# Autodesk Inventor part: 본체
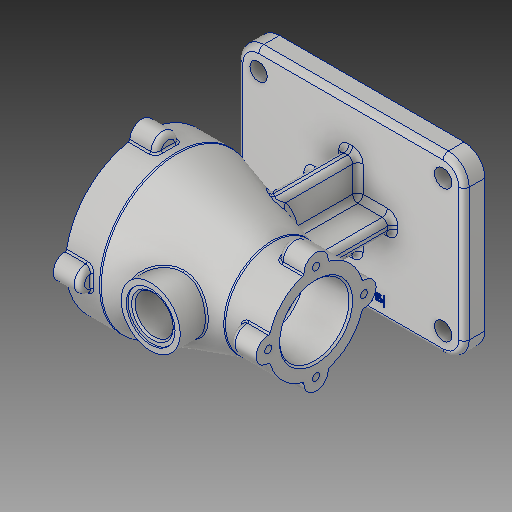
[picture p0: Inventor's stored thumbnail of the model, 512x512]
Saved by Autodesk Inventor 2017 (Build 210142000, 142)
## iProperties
Part Number: 본체
Material: 알루미늄 6061
Document SubType Name: Modeling
Designer: 222
Density: 2.7 g/cm^3
Appearance: 알루미늄 - 평지
Mass: 1030.13 g
Surface Area: 850.653 cm^2
Volume: 381.528 cm^3
Author: 222
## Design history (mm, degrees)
sketch "스케치1"
  geometry: L1 (-50, 0)-(50, 0); L2 (-50, 0)-(-50, 44); L3 (-50, 44)-(-30, 44); L4 (25, 27.5)-(50, 27.5); L5 (50, 27.5)-(50, 0); L6 (-30, 44)-(25, 27.5); 3 further points
  constraints: 12 end point, 2 midpoint, 2 perpendicular, 1 coincident, 1 horizontal, 1 parallel, 1 vertical
  dimensions: "d0" = 100 distance of L1.start L1.end; "d1" = 20 distance of L2.end L3.end; "d2" = 88 diameter of L3 L1; "d3" = 55 diameter of L4 L1; "d90" = 25 distance of L4.start L4.end
revolve "회전1" sketch "스케치1" stored, may be unused: angle "d5" = 90 deg
node "작업 평면1"
sketch "스케치2"
  geometry: L1 (-65, -50)-(65, -50); L2 (65, -50)-(65, 50); L3 (65, 50)-(-65, 50); L4 (-65, 50)-(-65, -50); L5 (-65, -50)-(65, 50); L6 (65, -50)-(-65, 50); 1 further point
  constraints: 12 end point, 2 midpoint, 2 parallel, 1 horizontal, 1 perpendicular
  dimensions: "d7" = 130 distance of L2.end L3.end; "d8" = 100 distance of L1.end L2.end
extrude "돌출1" join sketch "스케치2" distance "d9" = 12; taper "d10" = 0 deg
sketch "스케치3"
  geometry: L1 (-24, -4)-(24, -4); L2 (24, -4)-(24, 4); L3 (24, 4)-(-24, 4); L4 (-24, 4)-(-24, -4); L5 (-24, -4)-(24, 4); L6 (24, -4)-(-24, 4); L7 (4, -25)-(-4, -25); L8 (-4, -25)-(-4, 25); L9 (-4, 25)-(4, 25); L10 (4, 25)-(4, -25); L11 (4, -25)-(-4, 25); L12 (-4, -25)-(4, 25); 1 further point
  constraints: 24 end point, 4 midpoint, 4 parallel, 2 horizontal, 2 perpendicular
  dimensions: "d11" = 8 distance of L1.end L2.end; "d12" = 8 distance of L7.start L7.end; "d13" = 48 distance of L1.start L1.end; "d14" = 50 distance of L9.end L7.start
extrude "돌출2" join sketch "스케치3" stored distance "d15" = 12; taper "d16" = 0 deg
sketch "스케치4"
  geometry: L1 (50, 44)-(50, -44) reference; L2 (50, 0)-(-50, 0); L3 (-50, 27.5)-(-50, -27.5) reference; L4 (50, 0)-(50, 32); L5 (50, 32)-(27, 32); L6 (27, 32)-(27, 26); L7 (27, 26)-(-20, 26); L8 (-20, 26)-(-20, 20); L9 (-20, 20)-(-50, 20); L10 (-50, 0)-(-50, 20); 1 further point
  constraints: 16 end point, 5 perpendicular, 2 midpoint, 2 point on line, 1 horizontal
  dimensions: "d17" = 64 diameter of L5 L2; "d18" = 52 diameter of L7 L2; "d19" = 40 diameter of L9 L2; "d20" = 23 distance of L4.end L5.end; "d21" = 30 distance of L8.end L9.end
revolve "회전2" sketch "스케치4" stored, may be unused: angle "d22" = 90 deg
sketch "스케치5"
  geometry: C1 r 7 at (-27.5, 0); 2 further points
  constraints: 2 horizontal alignment, 1 centre point, 1 other
  dimensions: "d23" = 14 diameter of C1
extrude "돌출3" join sketch "스케치5" distance "d24" = 15; taper "d25" = 0 deg
sketch "스케치6"
  geometry: L1 (109.5, -50)-(97.5, -50) reference; L2 (97.5, -50)-(97.5, 50) reference; L3 (97.5, 50)-(109.5, 50) reference; L4 (109.5, 50)-(109.5, -50) reference; C1 r 20 at (27.5, 0) reference; A1 r 7 centre (27.5, -27.5) between (20.557, -26.609) and (34.443, -26.609) reference; A2 r 27.5 centre (27.5, 0) between (0.891, -6.943) and (20.557, -26.609) reference; A3 r 7 centre (0, 0) between (0.891, 6.943) and (0.891, -6.943) reference; A4 r 27.5 centre (27.5, 0) between (20.557, 26.609) and (0.891, 6.943) reference; A5 r 7 centre (27.5, 27.5) between (34.443, 26.609) and (20.557, 26.609) reference; A6 r 27.5 centre (27.5, 0) between (54.109, 6.943) and (34.443, 26.609) reference; A7 r 7 centre (55, 0) between (54.109, -6.943) and (54.109, 6.943) reference; A8 r 27.5 centre (27.5, 0) between (34.443, -26.609) and (54.109, -6.943) reference; 1 further point
hole "구멍1" sketch "스케치6" at (0, 0) diameter "d29" = 4.134; stored, may be unused: countersink angle "d33" = 90 deg, drill point angle "d35" = 118 deg; dims "d30" = 9, "d31" = 4, "d32" = 2, "d34" = 11
sketch "스케치7"
  geometry: C1 r 7 at (44, 0); 2 further points
  constraints: 2 horizontal alignment, 1 centre point, 1 other
  dimensions: "d39" = 14 diameter of C1
extrude "돌출4" join sketch "스케치7" distance "d40" = 15; taper "d41" = 0 deg
sketch "스케치8"
  geometry: A1 r 7 centre (0, 0) between (-0.557, -6.978) and (-0.557, 6.978) reference; 1 further point
hole "구멍2" sketch "스케치8" at (0, 0) diameter "d42" = 4.134; stored, may be unused: countersink angle "d46" = 90 deg, drill point angle "d48" = 118 deg; dims "d43" = 9, "d44" = 4, "d45" = 2, "d47" = 11
fillet "모깎기1" dims "d52" = 12
sketch "스케치9"
  geometry: L1 (65, 38)-(65, -38) reference; L2 (53, -50)-(-53, -50) reference; L3 (-65, -38)-(-65, 38) reference; L4 (-53, 50)-(53, 50) reference; L5 (24, 4)-(24, -4) reference; L6 (24, -4)-(4, -4) reference; L7 (4, -4)-(4, -25) reference; L8 (4, -25)-(-4, -25) reference; L9 (-4, -25)-(-4, -4) reference; L10 (-4, -4)-(-24, -4) reference; L11 (-24, -4)-(-24, 4) reference; L12 (-24, 4)-(-4, 4) reference; L13 (-4, 4)-(-4, 25) reference; L14 (-4, 25)-(4, 25) reference; L15 (4, 25)-(4, 4) reference; L16 (4, 4)-(24, 4) reference; C1 r 5 at (-53, 38); C2 r 5 at (-53, -38); C3 r 5 at (53, -38); C4 r 5 at (53, 38); A1 r 12 centre (53, 38) between (65, 38) and (53, 50) reference; A2 r 12 centre (53, -38) between (53, -50) and (65, -38) reference; A3 r 12 centre (-53, -38) between (-65, -38) and (-53, -50) reference; A4 r 12 centre (-53, 38) between (-53, 50) and (-65, 38) reference; 1 further point
  constraints: 4 centre point, 4 coincident
  dimensions: "d53" = 10 diameter of C1; "d54" = 10 diameter of C2; "d55" = 10 diameter of C3; "d56" = 10 diameter of C4
extrude "돌출5" cut sketch "스케치9" stored distance "d57" = 15; taper "d58" = 0 deg
node "작업 평면2"
sketch "스케치10"
  geometry: C1 r 17 at (0, 0); 1 further point
  constraints: 1 centre point, 1 coincident
  dimensions: "d60" = 34 diameter of C1
extrude "돌출6" join sketch "스케치10" stored distance "d61" = 15; taper "d62" = 0 deg
sketch "스케치11"
  geometry: 1 further point
hole "구멍3" sketch "스케치11" at (0, 0) diameter "d63" = 22; stored, may be unused: countersink angle "d67" = 90 deg, drill point angle "d69" = 118 deg; dims "d64" = 9, "d65" = 28, "d66" = 1, "d68" = 24.5
node "작업 평면3"
sketch "스케치12"
  geometry: L1 (-53, -50)-(53, -50) reference; 2 further points
  constraints: 1 vertical alignment, 1 other
  dimensions: "d71" = 10 distance from line of L1 point (0, -40)
feature "엠보싱1" sketch "스케치12" dims "d0" = 100, "d1" = 20, "d2" = 88, "d3" = 55, "d72" = 0.5, "d73" = 0, "d90" = 25
fillet "모깎기2" dims "d74" = 3
fillet "모깎기4" dims "d76" = 3
fillet "모깎기5" dims "d77" = 3
fillet "모깎기6" dims "d78" = 3
fillet "모깎기7" dims "d79" = 1
fillet "모깎기8" dims "d80" = 1
chamfer "모따기1" distance "d81" = 1; stored, may be unused: second distance "d82" = 2, angle "d83" = 45 deg
chamfer "모따기2" distance "d84" = 1; stored, may be unused: second distance "d85" = 2, angle "d86" = 45 deg
chamfer "모따기3" distance "d87" = 1; stored, may be unused: second distance "d88" = 2, angle "d89" = 45 deg
fillet "모깎기10" dims "d92" = 3
fillet "모깎기11" dims "d93" = 3
fillet "모깎기12" dims "d94" = 3
fillet "모깎기13" dims "d95" = 3
node "솔리드1"
pattern_circular "원형 패턴1" dims angle "d27" = 360 deg
pattern_circular "원형 패턴2" dims angle "d37" = 360 deg
pattern_circular "원형 패턴3" dims angle "d50" = 360 deg
node "절단 모서리 투영1"
node "절단 모서리 투영2"
other parameters: "d6" = -82, "d59" = 45, "d70" = 12.25
